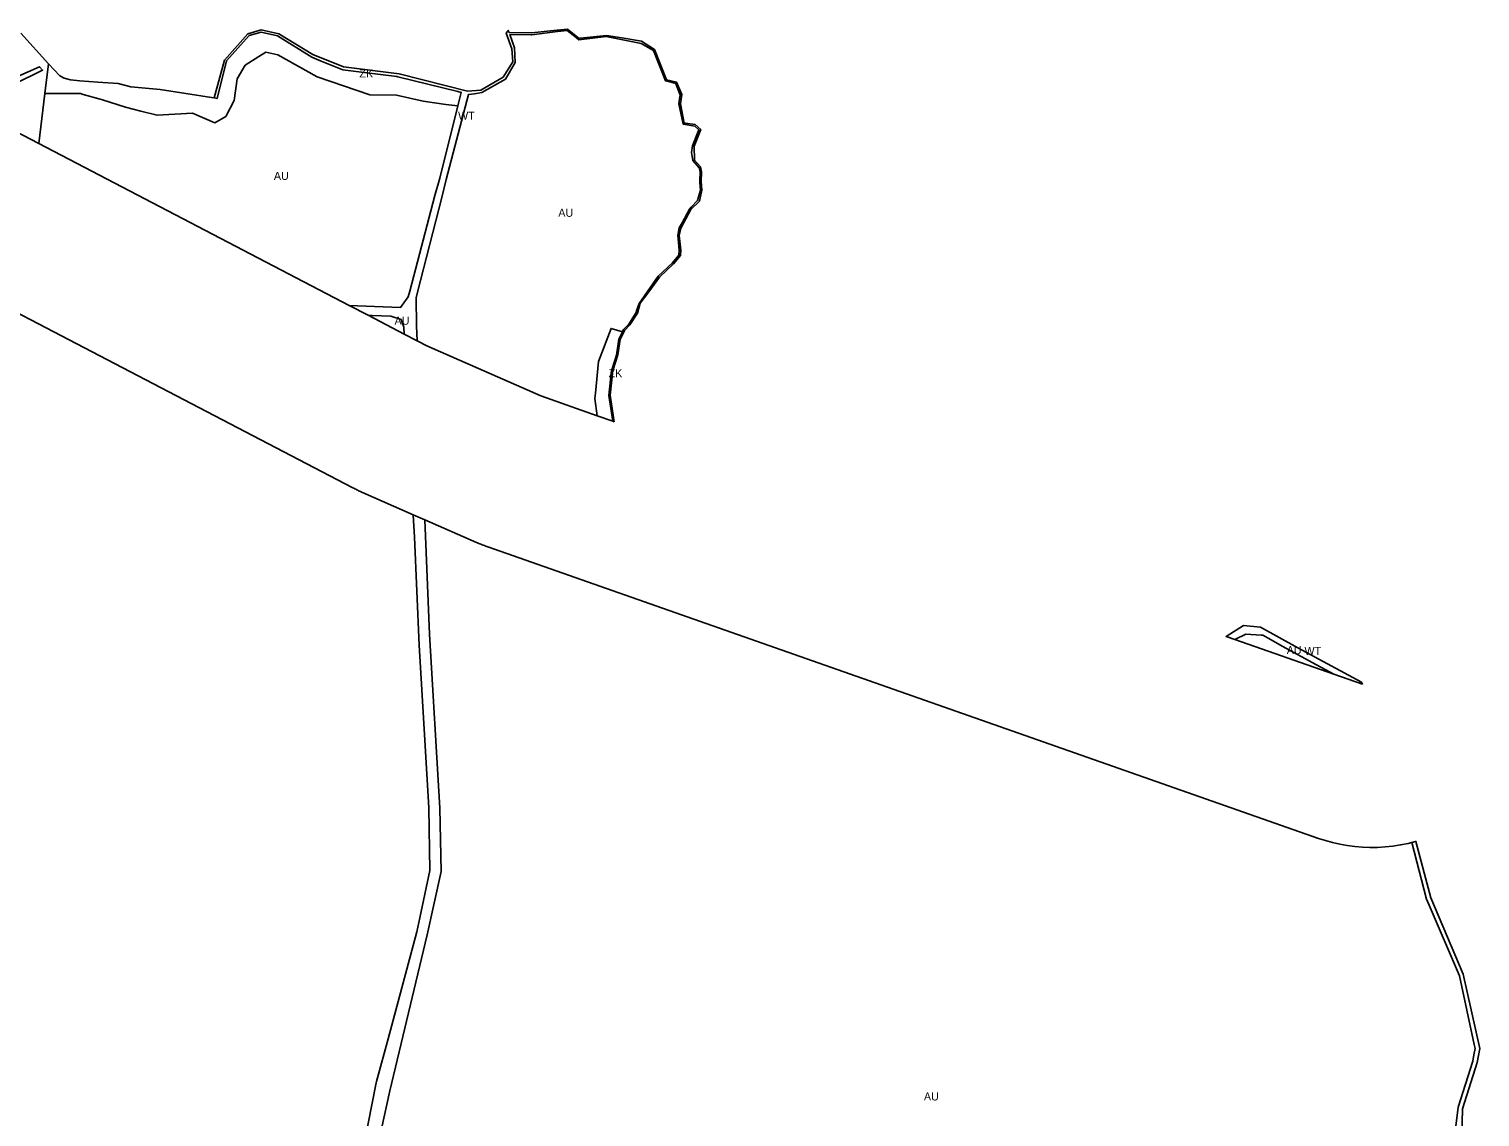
# Model space of a CAD drawing. Extents: x -545779 to -541342, y -1153413 to -1149956.
# Drawn here: x -542580 to -541673, y -1150681 to -1150001 of the extents above; entities that cross this region are included whole.
import ezdxf

# ---------------------------------------------------------------- set-up
doc = ezdxf.new("R2010")
doc.units = 0
for name, color, linetype in [('90640013', 7, 'Continuous'), ('90710013', 7, 'Continuous'), ('90750013', 7, 'Continuous'), ('90770013', 7, 'Continuous')]:
    doc.layers.add(name, color=color, linetype=linetype)

msp = doc.modelspace()

# ---------------------------------------------------------------- linework, layer by layer
at = {"layer": '90640013'}
for points in [[(-542214.387, -1150246.489), (-542214.387, -1150246.489), (-542215.348, -1150246.152), (-542217.81, -1150230.08), (-542216.06, -1150214.5), (-542215.94, -1150214.18), (-542212.92, -1150204.89), (-542211.6, -1150194.92), (-542209.32, -1150190.4), (-542208.59, -1150188.96), (-542205.25, -1150185.59), (-542200.68, -1150178.24), (-542200.56, -1150177.72), (-542200.43, -1150177.15), (-542198.76, -1150172.64), (-542190.22, -1150160.24), (-542186.93, -1150155.55), (-542178.07, -1150147.19), (-542174.09, -1150142.33), (-542173.87, -1150139.31), (-542174.45, -1150132.11), (-542174.61, -1150130.14), (-542173.76, -1150125.39), (-542172.02, -1150122.14), (-542167.44, -1150113.57), (-542166.4, -1150112.49), (-542162.3, -1150108.26), (-542161.11, -1150103.98), (-542160.48, -1150101.71), (-542160.72, -1150099.48), (-542161.02, -1150096.73), (-542160.97, -1150095.69), (-542160.7, -1150090.29), (-542161.41, -1150087.82), (-542165.24, -1150083.28), (-542165.92, -1150079.47), (-542166.13, -1150078.24), (-542165.59, -1150074.08), (-542161.96, -1150065.19), (-542161.49, -1150064.05), (-542164.16, -1150061.72), (-542171.44, -1150060.46), (-542174.07, -1150047.75), (-542173.35, -1150043.36), (-542173.2, -1150042.42), (-542175.92, -1150035.21), (-542182.39, -1150033.41), (-542189.93, -1150014.53), (-542197.52, -1150010.03), (-542219.54, -1150005.75), (-542236.6, -1150007.75), (-542238.24, -1150006.45), (-542243.87, -1150001.97), (-542249.8, -1150002.69), (-542265.99, -1150004.65), (-542266.25, -1150004.65), (-542279.65, -1150004.53), (-542276.79, -1150012.93), (-542276.24, -1150021.97), (-542282.46, -1150032.36), (-542297.15, -1150040.86), (-542301.71, -1150041.52), (-542305.52, -1150042.02), (-542319.34, -1150095.05), (-542322.14, -1150106.29), (-542337.43, -1150165.54), (-542338.26, -1150169.13), (-542337.99, -1150186.6), (-542337.573, -1150196.01), (-542345.651, -1150191.796), (-542345.84, -1150187.34), (-542347.64, -1150182.68), (-542353.93, -1150180.45), (-542365.6, -1150180.11), (-542368.248, -1150180.01), (-542380.138, -1150173.808), (-542364.21, -1150174.51), (-542347.94, -1150175.1), (-542343.24, -1150168.45), (-542342.14, -1150164.82), (-542326.43, -1150105.22), (-542323.32, -1150094.21), (-542312.08, -1150049.18), (-542309.98, -1150040.71), (-542312.2, -1150040.16), (-542349.72, -1150030.89), (-542350.23, -1150030.83), (-542370.64, -1150028.26), (-542384.04, -1150026.58), (-542397.6, -1150021.19), (-542403.3, -1150018.68), (-542424.74, -1150005.3), (-542435.05, -1150002.98), (-542442.42, -1150005.18), (-542456.69, -1150021.06), (-542462.57, -1150044.53), (-542464.34, -1150044.16), (-542457.9, -1150020.57), (-542443.31, -1150004.18), (-542435, -1150001.63), (-542424.09, -1150004.14), (-542402.64, -1150017), (-542383.64, -1150024.69), (-542348.88, -1150029.15), (-542306, -1150040.01), (-542297.68, -1150039.37), (-542283.76, -1150031.11), (-542277.77, -1150021.55), (-542278.43, -1150013.44), (-542282.03, -1150003.61), (-542280.63, -1150001.92), (-542280.14, -1150003.22), (-542265.94, -1150003.55), (-542254.33, -1150002.26), (-542243.68, -1150001.08), (-542236.35, -1150006.95), (-542235.69, -1150006.88), (-542219.23, -1150005.09), (-542209.59, -1150006.69), (-542197.28, -1150008.73), (-542189.24, -1150013.97), (-542181.69, -1150032.74), (-542175.46, -1150034.3), (-542172.16, -1150041.99), (-542173.07, -1150047.93), (-542170.67, -1150059.87), (-542169.98, -1150059.96), (-542163.76, -1150060.77), (-542160.41, -1150063.9), (-542164.55, -1150074.25), (-542164.27, -1150083.05), (-542160.51, -1150087.3), (-542159.8, -1150090.33), (-542160.11, -1150096.31), (-542159.6, -1150101.84), (-542161.15, -1150108.61), (-542166.47, -1150113.82), (-542172.76, -1150125.45), (-542173.76, -1150130.15), (-542172.87, -1150139.21), (-542173.05, -1150142.72), (-542177.43, -1150147.86), (-542186.23, -1150156.1), (-542192.79, -1150165.39), (-542198.21, -1150172.42), (-542199.91, -1150178.62), (-542204.65, -1150185.96), (-542208.03, -1150189.58), (-542210.73, -1150195.2), (-542212.11, -1150204.78), (-542215.3, -1150214.58), (-542216.94, -1150229.9)], [(-542618.903, -1150049.266), (-542622.665, -1150047.304), (-542619.24, -1150045.68), (-542608.45, -1150040.68), (-542602.01, -1150037.74), (-542594.82, -1150034.12), (-542573.48, -1150024.63), (-542571.57, -1150026.72), (-542589.76, -1150035.73), (-542601.29, -1150041.03)], [(-541746.857, -1150410.568), (-541746.857, -1150410.568), (-541764.792, -1150404.274), (-541775.53, -1150398.53), (-541797.17, -1150386.69), (-541803.98, -1150382.9), (-541809.2, -1150379.99), (-541810.21, -1150379.92), (-541819.71, -1150379.22), (-541826.641, -1150382.568), (-541832.131, -1150380.641), (-541821.25, -1150373.92), (-541810.54, -1150374.89), (-541787.38, -1150387.87), (-541747.45, -1150409.3)]]:
    msp.add_lwpolyline(points, close=True, dxfattribs=at)
for points in [[(-542370.7, -1150697.82), (-542363.21, -1150659.75), (-542362.95, -1150658.79), (-542355.74, -1150632.12), (-542337.68, -1150565.29), (-542335.84, -1150556.5), (-542329.65, -1150527.02), (-542330.19, -1150487.71), (-542332.68, -1150445.62), (-542336.2, -1150386.13), (-542339.31, -1150318.67), (-542340.023, -1150304.622), (-542332.684, -1150307.838), (-542329.92, -1150379.23), (-542323.43, -1150488.05), (-542322.47, -1150527.52), (-542331.21, -1150567.12), (-542354.69, -1150664.61), (-542359.8, -1150688.41)], [(-541688.75, -1150688.41), (-541687.19, -1150674.93), (-541678.02, -1150646.12), (-541677.29, -1150642.27), (-541676.53, -1150638.29), (-541677.1, -1150635.63), (-541686.26, -1150592.85), (-541705.23, -1150548.62), (-541706.85, -1150544.85), (-541716.114, -1150509.441), (-541713.76, -1150508.841), (-541713.481, -1150508.755), (-541704.27, -1150544.01), (-541683.98, -1150591.73), (-541673.47, -1150638.23), (-541675.28, -1150647.01), (-541684.35, -1150675.91), (-541684.91, -1150693.21)]]:
    msp.add_lwpolyline(points, dxfattribs=at)
at = {"layer": '90710013'}
for points in [[(-542462.57, -1150044.53), (-542456.69, -1150021.06), (-542442.42, -1150005.18), (-542435.05, -1150002.98), (-542424.74, -1150005.3), (-542403.3, -1150018.68), (-542397.6, -1150021.19), (-542384.04, -1150026.58), (-542370.64, -1150028.26), (-542350.23, -1150030.83), (-542349.72, -1150030.89), (-542312.2, -1150040.16), (-542309.98, -1150040.71), (-542312.08, -1150049.18), (-542319.58, -1150048.17), (-542333.79, -1150046.26), (-542350.43, -1150042.46), (-542367.21, -1150042.29), (-542400.08, -1150031.03), (-542424.61, -1150017.21), (-542432.19, -1150015.63), (-542436.5, -1150018.33), (-542445.04, -1150023.68), (-542450.09, -1150032.26), (-542451.95, -1150045.83), (-542457.08, -1150055.7), (-542463.98, -1150059.65), (-542477.95, -1150053.7), (-542500.06, -1150055.02), (-542510.29, -1150052.39), (-542519.82, -1150049.94), (-542534.23, -1150045.29), (-542535.58, -1150044.86), (-542546.19, -1150041.92), (-542547.98, -1150041.42), (-542556.62, -1150041.43), (-542570.18, -1150041.45), (-542567.91, -1150022.74), (-542560.89, -1150030.36), (-542558.09, -1150031.74), (-542554.09, -1150032.87), (-542548.28, -1150033.49), (-542537.17, -1150034.26), (-542524.38, -1150035.08), (-542516.56, -1150037.16), (-542498.22, -1150038.93), (-542466.12, -1150043.78), (-542464.34, -1150044.16)], [(-542215.348, -1150246.152), (-542224.982, -1150242.771), (-542226.55, -1150231.91), (-542226.22, -1150228.63), (-542226.22, -1150228.63), (-542224.22, -1150208.77), (-542216.41, -1150188.16), (-542209.32, -1150190.4), (-542211.6, -1150194.92), (-542212.92, -1150204.89), (-542215.94, -1150214.18), (-542216.06, -1150214.5), (-542217.81, -1150230.08)]]:
    msp.add_lwpolyline(points, close=True, dxfattribs=at)
at = {"layer": '90750013'}
for points in [[(-542224.982, -1150242.771), (-542260.315, -1150230.37), (-542331.51, -1150199.172), (-542337.573, -1150196.01), (-542337.99, -1150186.6), (-542338.26, -1150169.13), (-542337.43, -1150165.54), (-542322.14, -1150106.29), (-542319.34, -1150095.05), (-542305.52, -1150042.02), (-542301.71, -1150041.52), (-542297.15, -1150040.86), (-542282.46, -1150032.36), (-542276.24, -1150021.97), (-542276.79, -1150012.93), (-542279.65, -1150004.53), (-542266.25, -1150004.65), (-542265.99, -1150004.65), (-542249.8, -1150002.69), (-542243.87, -1150001.97), (-542238.24, -1150006.45), (-542236.6, -1150007.75), (-542219.54, -1150005.75), (-542197.52, -1150010.03), (-542189.93, -1150014.53), (-542182.39, -1150033.41), (-542175.92, -1150035.21), (-542173.2, -1150042.42), (-542173.35, -1150043.36), (-542174.07, -1150047.75), (-542171.44, -1150060.46), (-542164.16, -1150061.72), (-542161.49, -1150064.05), (-542161.96, -1150065.19), (-542165.59, -1150074.08), (-542166.13, -1150078.24), (-542165.92, -1150079.47), (-542165.24, -1150083.28), (-542161.41, -1150087.82), (-542160.7, -1150090.29), (-542160.97, -1150095.69), (-542161.02, -1150096.73), (-542160.72, -1150099.48), (-542160.48, -1150101.71), (-542161.11, -1150103.98), (-542162.3, -1150108.26), (-542166.4, -1150112.49), (-542167.44, -1150113.57), (-542172.02, -1150122.14), (-542173.76, -1150125.39), (-542174.61, -1150130.14), (-542174.45, -1150132.11), (-542173.87, -1150139.31), (-542174.09, -1150142.33), (-542178.07, -1150147.19), (-542186.93, -1150155.55), (-542190.22, -1150160.24), (-542198.76, -1150172.64), (-542200.43, -1150177.15), (-542200.56, -1150177.72), (-542200.68, -1150178.24), (-542205.25, -1150185.59), (-542208.59, -1150188.96), (-542209.32, -1150190.4), (-542216.41, -1150188.16), (-542224.22, -1150208.77), (-542226.22, -1150228.63), (-542226.22, -1150228.63), (-542226.55, -1150231.91)], [(-542380.138, -1150173.808), (-542573.976, -1150072.7), (-542570.18, -1150041.45), (-542556.62, -1150041.43), (-542547.98, -1150041.42), (-542546.19, -1150041.92), (-542535.58, -1150044.86), (-542534.23, -1150045.29), (-542519.82, -1150049.94), (-542510.29, -1150052.39), (-542500.06, -1150055.02), (-542477.95, -1150053.7), (-542463.98, -1150059.65), (-542457.08, -1150055.7), (-542451.95, -1150045.83), (-542450.09, -1150032.26), (-542445.04, -1150023.68), (-542436.5, -1150018.33), (-542432.19, -1150015.63), (-542424.61, -1150017.21), (-542400.08, -1150031.03), (-542367.21, -1150042.29), (-542350.43, -1150042.46), (-542333.79, -1150046.26), (-542319.58, -1150048.17), (-542312.08, -1150049.18), (-542323.32, -1150094.21), (-542326.43, -1150105.22), (-542342.14, -1150164.82), (-542343.24, -1150168.45), (-542347.94, -1150175.1), (-542364.21, -1150174.51)], [(-542345.651, -1150191.796), (-542368.248, -1150180.01), (-542365.6, -1150180.11), (-542353.93, -1150180.45), (-542347.64, -1150182.68), (-542345.84, -1150187.34)], [(-541764.792, -1150404.274), (-541826.641, -1150382.568), (-541819.71, -1150379.22), (-541810.21, -1150379.92), (-541809.2, -1150379.99), (-541803.98, -1150382.9), (-541797.17, -1150386.69), (-541775.53, -1150398.53)]]:
    msp.add_lwpolyline(points, close=True, dxfattribs=at)
for points in [[(-542786.029, -1150074.879), (-542377.782, -1150287.823), (-542377.175, -1150288.137), (-542376.566, -1150288.447), (-542375.955, -1150288.752), (-542375.342, -1150289.054), (-542374.727, -1150289.351), (-542374.109, -1150289.644), (-542373.49, -1150289.933), (-542372.869, -1150290.218), (-542372.246, -1150290.499), (-542371.622, -1150290.775), (-542340.023, -1150304.622), (-542339.31, -1150318.67), (-542336.2, -1150386.13), (-542332.68, -1150445.62), (-542330.19, -1150487.71), (-542329.65, -1150527.02), (-542335.84, -1150556.5), (-542337.68, -1150565.29), (-542355.74, -1150632.12), (-542362.95, -1150658.79), (-542363.21, -1150659.75), (-542370.7, -1150697.82)], [(-542359.8, -1150688.41), (-542354.69, -1150664.61), (-542331.21, -1150567.12), (-542322.47, -1150527.52), (-542323.43, -1150488.05), (-542329.92, -1150379.23), (-542332.684, -1150307.838), (-542300.479, -1150321.95), (-542299.781, -1150322.253), (-542299.081, -1150322.55), (-542298.378, -1150322.843), (-542297.673, -1150323.13), (-542296.966, -1150323.411), (-542296.257, -1150323.687), (-542295.546, -1150323.958), (-542294.833, -1150324.224), (-542294.118, -1150324.484), (-542293.401, -1150324.738), (-541774.355, -1150506.897), (-541770.009, -1150508.313), (-541765.559, -1150509.541), (-541761.017, -1150510.572), (-541756.397, -1150511.398), (-541751.713, -1150512.011), (-541746.978, -1150512.405), (-541742.208, -1150512.577), (-541737.42, -1150512.522), (-541732.628, -1150512.238), (-541727.851, -1150511.726), (-541723.103, -1150510.987), (-541718.401, -1150510.024), (-541716.114, -1150509.441), (-541706.85, -1150544.85), (-541705.23, -1150548.62), (-541686.26, -1150592.85), (-541677.1, -1150635.63), (-541676.53, -1150638.29), (-541677.29, -1150642.27), (-541678.02, -1150646.12), (-541687.19, -1150674.93), (-541688.75, -1150688.41)]]:
    msp.add_lwpolyline(points, dxfattribs=at)
at = {"layer": '90770013'}
for points in [[(-542585.14, -1150003.72), (-542567.91, -1150022.74), (-542570.18, -1150041.45), (-542573.976, -1150072.7), (-542618.903, -1150049.266)], [(-542589.76, -1150035.73), (-542571.57, -1150026.72), (-542573.48, -1150024.63), (-542594.82, -1150034.12)]]:
    msp.add_lwpolyline(points, dxfattribs=at)

# ---------------------------------------------------------------- texts
at = {"layer": '90640013'}
for p in [(-542311.97, -1150057.753), (-541783.124, -1150392.244)]:
    msp.add_text('WT', height=5, rotation=360, dxfattribs=at).set_placement(p)
at = {"layer": '90710013'}
for rotation, p in [(0, (-542373.624, -1150031.315)), (360, (-542217.935, -1150218.714))]:
    msp.add_text('ZK', height=5, rotation=rotation, dxfattribs=at).set_placement(p)
at = {"layer": '90750013'}
for rotation, p in [(0, (-542427.085, -1150095.365)), (0, (-542351.672, -1150185.903)), (0, (-541794.207, -1150391.747)), (360, (-542020.919, -1150670.694))]:
    msp.add_text('AU', height=5, rotation=rotation, dxfattribs=at).set_placement(p)
msp.add_text('AU', height=5, dxfattribs=at).set_placement((-542249.37, -1150118.425))

doc.saveas('drawing.dxf')
